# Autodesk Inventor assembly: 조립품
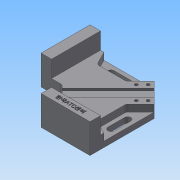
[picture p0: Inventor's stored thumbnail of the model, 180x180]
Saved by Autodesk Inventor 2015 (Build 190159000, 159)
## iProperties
Created: 2019-04
Part Number: 조립품
Document SubType Name: Assembly
Designer: user
Author: user
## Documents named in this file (2)
- C:\Users\user\Desktop\490407V1034\조립품.iam
- C:\Users\user\Desktop\490407V1034\본체.ipt
